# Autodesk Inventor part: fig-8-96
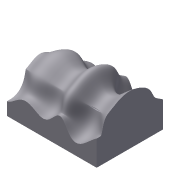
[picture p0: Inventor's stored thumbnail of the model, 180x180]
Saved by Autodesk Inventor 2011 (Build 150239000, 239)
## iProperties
Shininess: 64.0
Length Units: 11269
Angle Units: 11279
Time Units: 11290
Mass Units: 11283
Length Display Precision: 3
Angle Display Precision: 2
Compacted: True
Part Number: fig-8-96
Document SubType Name: Modeling
Created: 2002-12
Designer: deepak
Density: 1 g/cm^3
Density: 0.0
Volumn: 0.0
Area: 0.0
PropertySet Name: Model Information
Control State: 0
Master: False
Checked Out: False
Author: deepak
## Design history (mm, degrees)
sketch "Sketch1"
  geometry: L1 (-34.987, 25.636)-(31.934, 25.636); L2 (31.934, 25.636)-(31.934, -23.728); L3 (31.934, -23.728)-(-34.987, -23.728); L4 (-34.987, -23.728)-(-34.987, 25.636)
  constraints: 8 end point, 2 parallel, 1 horizontal, 1 perpendicular
extrude "Extrusion1" new body sketch "Sketch1" distance "d0" = 25; taper "d1" = 0 deg
sketch "Sketch2"
  geometry: 14 further points
  constraints: 14 other
workplane "Work Plane1"
sketch "Sketch3"
  geometry: 8 further points
  constraints: 8 other
feature "SweepSrf1" sketch "Sketch3" dims "d2" = 0
feature "Replace Face3"
body "Solid1"
body "Srf1"
